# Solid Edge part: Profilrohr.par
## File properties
Username: ahadarics
Dokumentum tartalom típus: 0
Author: ahadarics
Last saved by: ahadarics
Revision: 78
Sűrűség: 0,000 kg/m^3
Pontosság: 0,990
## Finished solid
Body 1: solid body, 6 faces, 6 edges, 0 vertices.
  Faces by surface: cone 2, cylinder 2, plane 2
  Edges by curve: circle 6
Bounding box of the edges (mm): 21.270 x 21.270 x 82.000, from (-10.635, -10.635, -61) to (10.635, 10.635, 21).
Cylindrical faces by radius (mm): R10 x1, R10.635 x1
Conical faces (half-angle, radius in mm at the cone's reference point): 15 deg R10.067 x2
Planar faces by outward normal: +z 1, -z 1
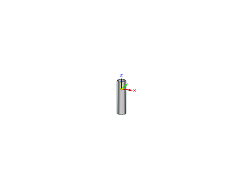
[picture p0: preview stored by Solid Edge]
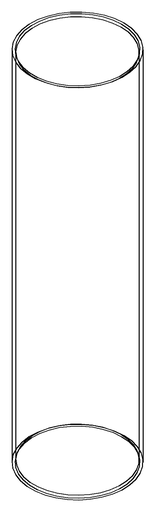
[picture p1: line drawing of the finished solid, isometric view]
